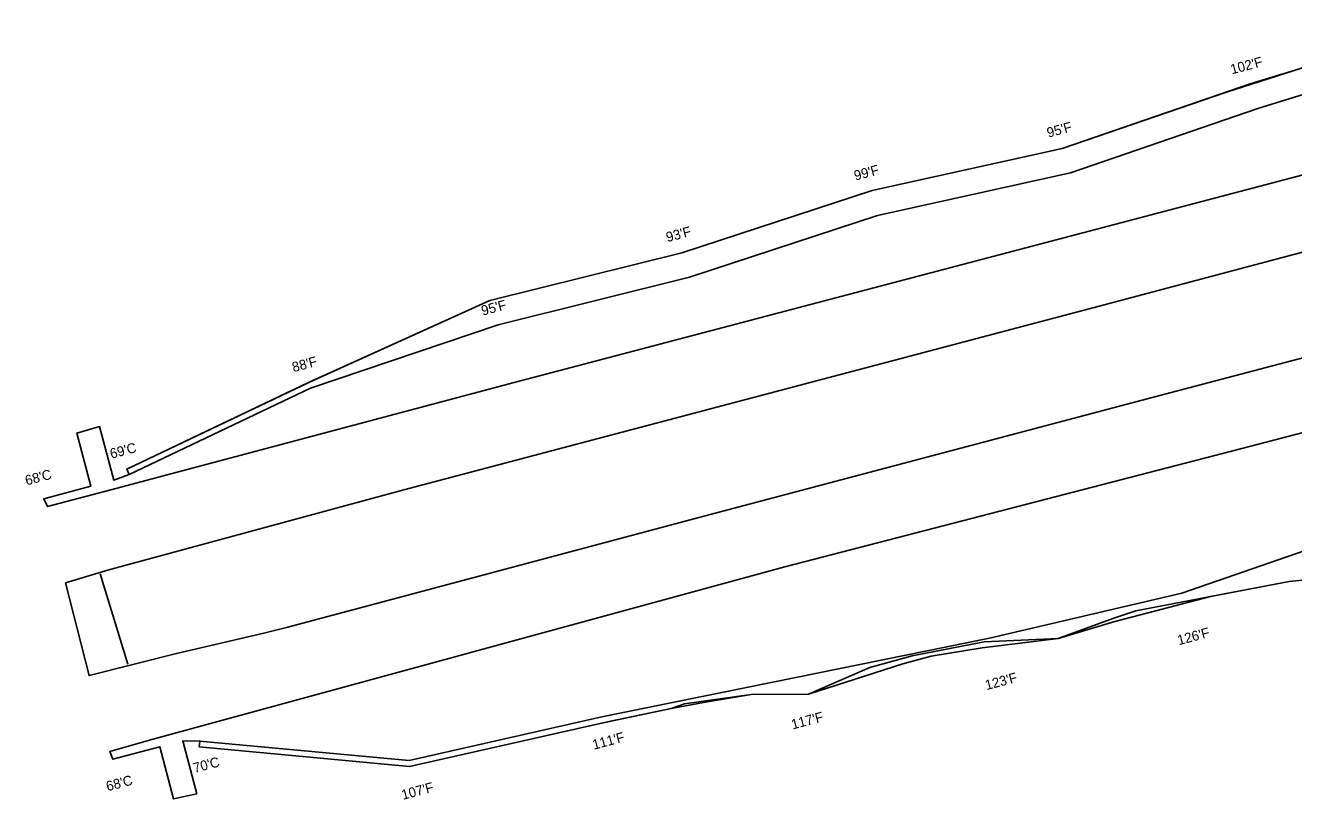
# Model space of a CAD drawing. Extents: x 2110378 to 2113376, y 867150 to 868109.
# Drawn here: x 2110378 to 2111021, y 867150 to 867542 of the extents above; entities that cross this region are included whole.
import ezdxf

# ---------------------------------------------------------------- set-up
doc = ezdxf.new("R2010")
doc.units = 0
for name, color, linetype in [('RD_PD_CstnLmt', 7, 'Continuous'), ('RD_PD_DR_ErosCtrl', 7, 'Continuous'), ('RD_PD_TX_CstnLmt', 7, 'Continuous'), ('RD_Sketch1', 7, 'Continuous')]:
    doc.layers.add(name, color=color, linetype=linetype)

msp = doc.modelspace()

# ---------------------------------------------------------------- linework, layer by layer
at = {"layer": 'RD_PD_CstnLmt'}
for p, q in [((2111002.71, 867500.26), (2111098.35, 867529.73)), ((2110907.88, 867467.73), (2111002.71, 867500.26)), ((2110810.18, 867446.01), (2110907.88, 867467.73)), ((2110714.99, 867414.85), (2110810.18, 867446.01)), ((2110617.92, 867390.77), (2110714.99, 867414.85)), ((2110522.97, 867358.68), (2110617.92, 867390.77)), ((2110431.1, 867314.97), (2110522.97, 867358.68)), ((2110964.32, 867254.8), (2111059.04, 867287.75)), ((2110430.44, 867218.87), (2110416.31, 867264.71)), ((2110866.9, 867232.03), (2110964.32, 867254.8)), ((2110768.72, 867212.12), (2110866.9, 867232.03)), ((2110670.55, 867192.2), (2110768.72, 867212.12)), ((2110572.95, 867170.11), (2110670.55, 867192.2)), ((2110465.34, 867153.23), (2110458.19, 867180.17)), ((2110458.19, 867180.17), (2110466.87, 867180.03)), ((2110466.87, 867180.03), (2110572.95, 867170.11)), ((2110422.77, 867170.78), (2110446.6, 867177.1)), ((2110446.6, 867177.1), (2110453.59, 867150.72)), ((2110453.59, 867150.72), (2110465.34, 867153.23))]:
    msp.add_line(p, q, dxfattribs=at)
msp.add_lwpolyline([(2110387.81, 867302.67), (2110411.64, 867308.98), (2110404.51, 867335.88), (2110416.05, 867339.19), (2110423.24, 867312.06), (2110431.1, 867314.97)], dxfattribs=at)
at = {"layer": 'RD_PD_DR_ErosCtrl'}
for p, q in [((2110998.88, 867512.69), (2111095.14, 867542.33)), ((2110903.66, 867480.03), (2110998.88, 867512.69)), ((2110807.36, 867458.7), (2110903.66, 867480.03)), ((2110710.95, 867427.2), (2110807.36, 867458.7)), ((2110613.75, 867403.09), (2110710.95, 867427.2)), ((2110521.84, 867361.47), (2110613.75, 867403.09)), ((2110429.81, 867317.68), (2110521.84, 867361.47)), ((2110573.15, 867167.08), (2110674.94, 867190.12)), ((2110466.59, 867177.05), (2110573.15, 867167.08))]:
    msp.add_line(p, q, dxfattribs=at)
msp.add_lwpolyline([(2110674.94, 867190.12), (2110705.68, 867196.45), (2110723.79, 867199.86), (2110746.17, 867203.57), (2110775.12, 867203.67), (2110822.94, 867219.17), (2110837.28, 867223.06), (2110863.13, 867227.2), (2110901.69, 867231.9), (2110930.34, 867240.47), (2110943.36, 867243.87), (2110978.83, 867253.13), (2111018.72, 867260.75), (2111043.46, 867263.39), (2111087.85, 867273.53)], dxfattribs=at)
at = {"layer": 'RD_Sketch1'}
for points in [[(2111153.33, 867500.21), (2110872.46, 867426.33), (2110626.1, 867361.52), (2110421.77, 867307.27), (2110389.64, 867298.75), (2110387.81, 867302.67), (2110411.64, 867308.98), (2110404.51, 867335.88), (2110416.05, 867339.19), (2110423.24, 867312.06), (2110431.1, 867314.97), (2110429.81, 867317.68), (2110522.45, 867361.64), (2110613.75, 867403.09), (2110710.95, 867427.2), (2110807.36, 867458.7), (2110903.66, 867480.03), (2110986.86, 867508.56), (2111025.48, 867520.88)], [(2111221.14, 867387.23), (2110999.3, 867329.24), (2110763.12, 867268.17), (2110442.48, 867180.72), (2110421.22, 867174.75), (2110422.77, 867170.78), (2110446.6, 867177.1), (2110453.59, 867150.72), (2110465.34, 867153.23), (2110458.19, 867180.17), (2110466.87, 867180.03), (2110466.59, 867177.05), (2110573.15, 867167.08), (2110671.14, 867189.26), (2110705.68, 867196.45), (2110712.44, 867198.88), (2110746.17, 867203.57), (2110775.12, 867203.67), (2110806.25, 867217.31), (2110827.76, 867223.12), (2110864.13, 867230.23), (2110901.69, 867231.9), (2110929.86, 867242.28), (2110941.07, 867246.01), (2111018.72, 867260.75), (2111043.46, 867263.39)]]:
    msp.add_lwpolyline(points, dxfattribs=at)
msp.add_lwpolyline([(2110398.77, 867260.06), (2110410.77, 867213.13), (2110455.1, 867224.38), (2110499.31, 867234.55), (2110511.52, 867237.66), (2110722.77, 867294.01), (2110955.73, 867355.66), (2111110.41, 867396.31), (2111205.39, 867422.98), (2111262.22, 867437.62), (2111249.46, 867485.75), (2111196.19, 867471.78), (2111183.06, 867469.32), (2110919.88, 867399.53), (2110570.18, 867307.24), (2110420.71, 867266.63)], close=True, dxfattribs=at)

# ---------------------------------------------------------------- texts
at = {"layer": 'RD_PD_TX_CstnLmt'}
for s, p in [("102'F", (2110989.66, 867517.5)), ("95'F", (2110896.65, 867485.45)), ("99'F", (2110798.96, 867463.72)), ("93'F", (2110703.76, 867432.56)), ("95'F", (2110610.17, 867395.36)), ("88'F", (2110514.31, 867366.73)), ("69'C", (2110422.07, 867322.92)), ("68'C", (2110379.11, 867309.39)), ("126'F", (2110962.79, 867228.53)), ("123'F", (2110865.37, 867205.77)), ("117'F", (2110767.2, 867185.86)), ("111'F", (2110666.46, 867175.6)), ("70'C", (2110464.24, 867163.82)), ("68'C", (2110420.14, 867154.57)), ("107'F", (2110569.74, 867150.22))]:
    msp.add_text(s, height=5, rotation=14.84478, dxfattribs=at).set_placement(p)

doc.saveas('drawing.dxf')
